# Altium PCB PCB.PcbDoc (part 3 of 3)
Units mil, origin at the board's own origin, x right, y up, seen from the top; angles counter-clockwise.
Board outline 5900 x 2310 mil, 2 copper layers (Top Layer, Bottom Layer), stack 62 mil thick; 158 components, 83 nets, 407 pads, 547 vias.
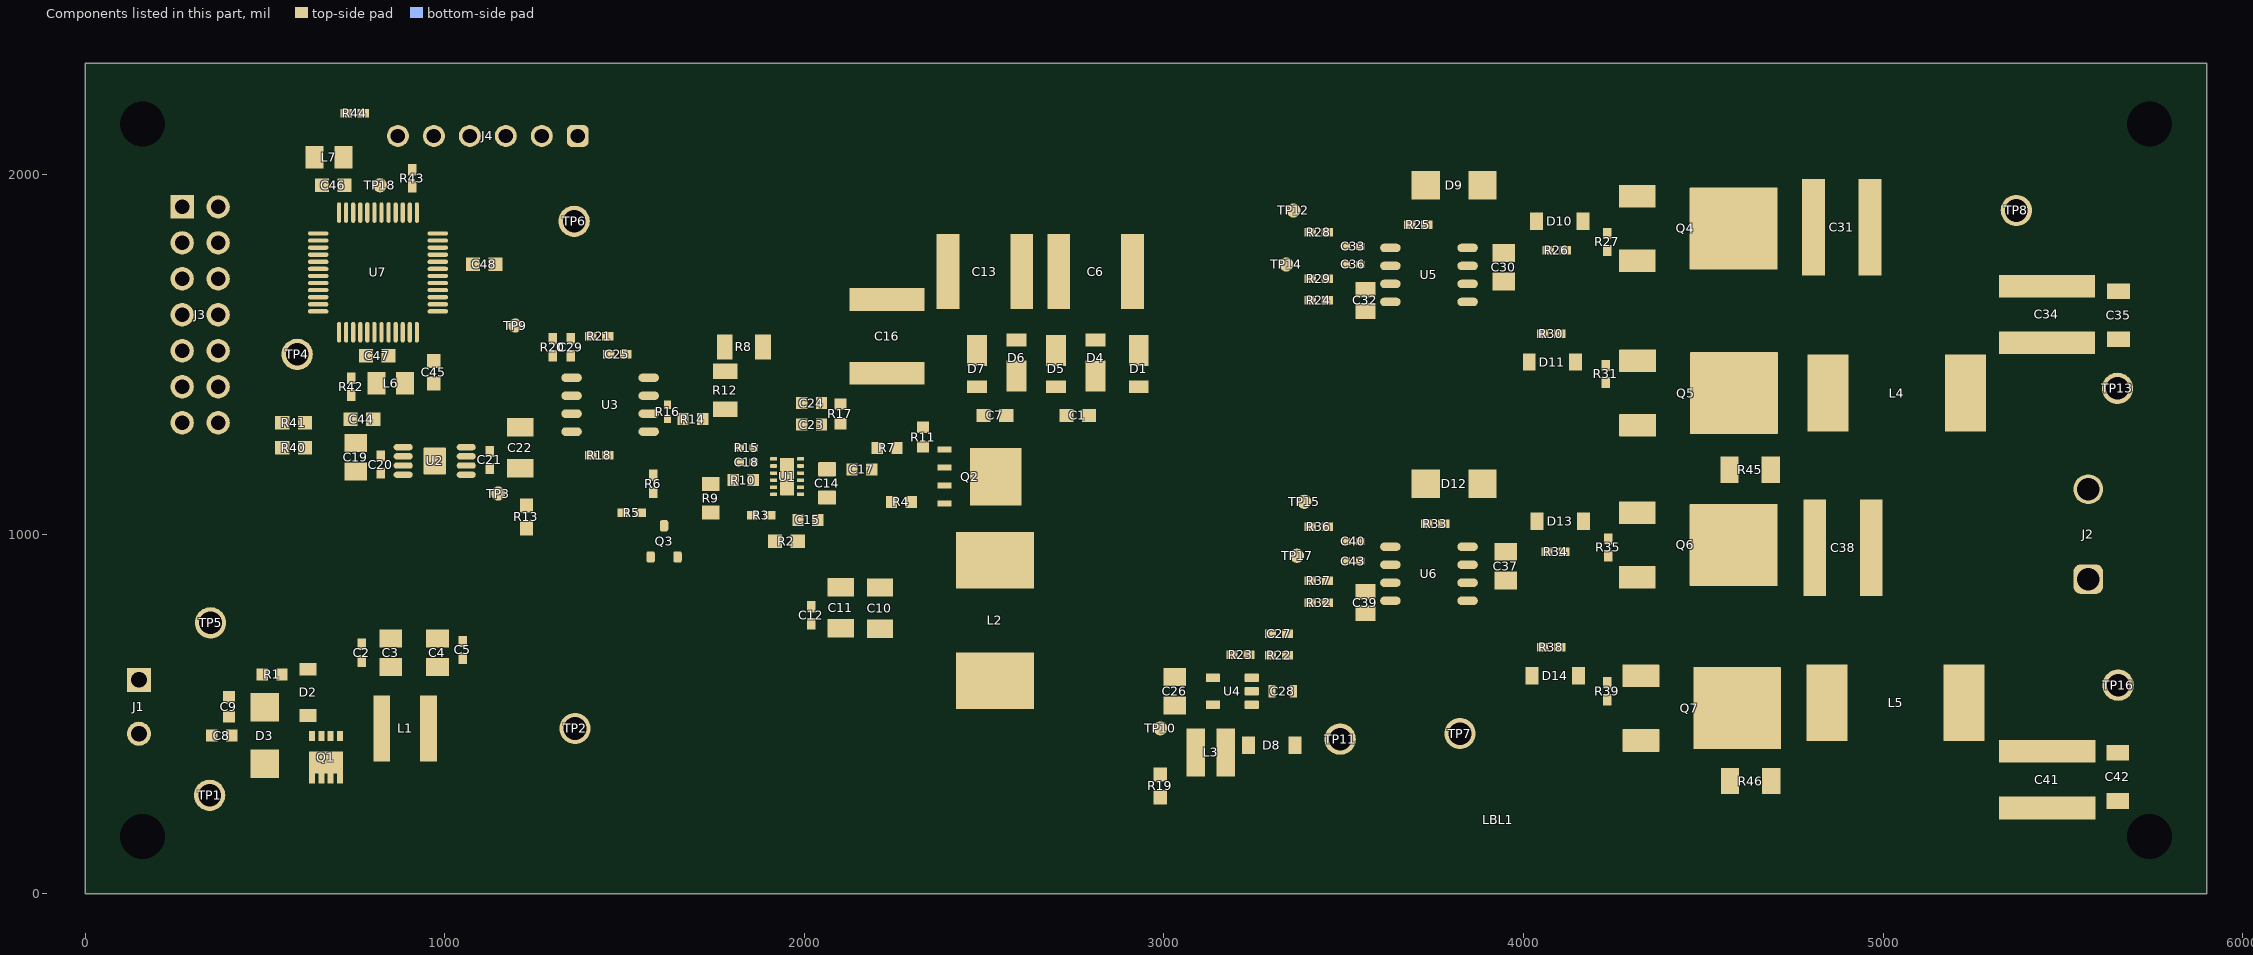
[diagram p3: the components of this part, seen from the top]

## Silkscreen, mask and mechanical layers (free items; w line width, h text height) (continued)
Drill Drawing:
  circle w10: c5415.05,3677.44 r27.63
  circle w10: c5415.05,3428.8 r16.58
  circle w10: c5415.05,3428.8 r27.63
  lines w10: 5387.43,3580.75 5442.68,3580.75 5415.05,3525.5 5387.43,3580.75 ; 5387.43,3774.14 5387.43,3787.95 5401.24,3801.76 5387.43,3815.58 5387.43,3829.39 5401.24,3829.39 5415.05,3815.58 5428.87,3829.39 5442.68,3829.39 5442.68,3815.58 5428.87,3801.76 5442.68,3787.95 5442.68,3774.14 5428.87,3774.14 5415.05,3787.95 5401.24,3774.14 5387.43,3774.14 ; 5387.43,3898.46 5442.68,3898.46 5442.68,3953.71 5387.43,3953.71 5387.43,3898.46 ; 5387.43,4022.78 5442.68,4022.78 5442.68,4078.03 5387.43,4078.03 5387.43,4022.78 ; 5387.43,4174.72 5415.05,4147.1 5442.68,4174.72 5415.05,4202.35 5387.43,4174.72 ; 5387.43,4271.42 5415.05,4285.23 5442.68,4271.42 5428.87,4299.04 5442.68,4326.67 5415.05,4312.86 5387.43,4326.67 5401.24,4299.04 5387.43,4271.42 ; 5387.43,4409.55 5401.24,4409.55 5401.24,4395.74 5428.87,4395.74 5428.87,4409.55 5442.68,4409.55 5442.68,4437.18 5428.87,4437.18 5428.87,4450.99 5401.24,4450.99 5401.24,4437.18 5387.43,4437.18 5387.43,4409.55 ; 5398.48,4033.83 5431.63,4033.83 5431.63,4066.98 5398.48,4066.98 5398.48,4033.83
  lines w12: 5337.34,3363.88 8568.82,3363.88 ; 5337.34,4482.76 8568.82,4482.76 ; 5675.2,3239.56 5675.2,4607.08 ; 6007.2,3239.56 6007.2,4607.08 ; 6643.76,3239.56 6643.76,4607.08 ; 6902.9,3239.56 6902.9,4607.08 ; 7278.06,3239.56 7278.06,4607.08 ; 8002.39,3239.56 8002.39,4607.08 ; 5337.34,3239.56 8568.82,3239.56 8568.82,4607.08 5337.34,4607.08 5337.34,3239.56
  text "Symbol" at 5411.93,4520.06 h72
  text "Quantity" at 5712.49,4520.06 h72
  text "Finished Hole Size" at 6044.5,4520.06 h72
  text "Plated" at 6681.06,4520.06 h72
  text "Hole Type" at 6940.2,4520.06 h72
  text "Drill Layer Pair" at 7315.36,4520.06 h72
  text "Hole Tolerance" at 8039.69,4520.06 h72
  text "8" at 5712.49,4395.74 h60
  text "7.87mil (0.200mm)" at 6044.5,4395.74 h60
  text "PTH" at 6681.06,4395.74 h60
  text "Round" at 6940.2,4395.74 h60
  text "Top Layer - Bottom Layer" at 7315.36,4395.74 h60
  text "517" at 5712.49,4271.42 h60
  text "10.00mil (0.254mm)" at 6044.5,4271.42 h60
  text "PTH" at 6681.06,4271.42 h60
  text "Round" at 6940.2,4271.42 h60
  text "Top Layer - Bottom Layer" at 7315.36,4271.42 h60
  text "22" at 5712.49,4147.1 h60
  text "28.00mil (0.711mm)" at 6044.5,4147.1 h60
  text "PTH" at 6681.06,4147.1 h60
  text "Round" at 6940.2,4147.1 h60
  text "Top Layer - Bottom Layer" at 7315.36,4147.1 h60
  text "14" at 5712.49,4022.78 h60
  text "40.00mil (1.016mm)" at 6044.5,4022.78 h60
  text "PTH" at 6681.06,4022.78 h60
  text "Round" at 6940.2,4022.78 h60
  text "Top Layer - Bottom Layer" at 7315.36,4022.78 h60
  text "6" at 5712.49,3898.46 h60
  text "40.16mil (1.020mm)" at 6044.5,3898.46 h60
  text "PTH" at 6681.06,3898.46 h60
  text "Round" at 6940.2,3898.46 h60
  text "Top Layer - Bottom Layer" at 7315.36,3898.46 h60
  text "2" at 5712.49,3774.14 h60
  text "43.31mil (1.100mm)" at 6044.5,3774.14 h60
  text "PTH" at 6681.06,3774.14 h60
  text "Round" at 6940.2,3774.14 h60
  text "Top Layer - Bottom Layer" at 7315.36,3774.14 h60
  text "2" at 5712.49,3649.82 h60
  text "62.99mil (1.600mm)" at 6044.5,3649.82 h60
  text "PTH" at 6681.06,3649.82 h60
  text "Round" at 6940.2,3649.82 h60
  text "Top Layer - Bottom Layer" at 7315.36,3649.82 h60
  text "10" at 5712.49,3525.5 h60
  text "63.00mil (1.600mm)" at 6044.5,3525.5 h60
  text "PTH" at 6681.06,3525.5 h60
  text "Round" at 6940.2,3525.5 h60
  text "Top Layer - Bottom Layer" at 7315.36,3525.5 h60
  text "4" at 5712.49,3401.18 h60
  text "125.00mil (3.175mm)" at 6044.5,3401.18 h60
  text "PTH" at 6681.06,3401.18 h60
  text "Round" at 6940.2,3401.18 h60
  text "Top Layer - Bottom Layer" at 7315.36,3401.18 h60
  text "585 Total" at 5712.49,3276.86 h60
  text ".Layer_Name" at 577,-858.49 h60
M17 Embedded Cavity:
  text ".Layer_Name" at 577,-858.49 h60
M18 Embedded Assembly:
  text ".Layer_Name" at 577,-858.49 h60
M19 Embedded Keepout:
  text ".Layer_Name" at 577,-858.49 h60

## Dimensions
0,-400 to 1000,-400 on M2 Board Dimensions
0,0 to 5900,-40 on M2 Board Dimensions
0,0 to -120,2310 on M2 Board Dimensions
